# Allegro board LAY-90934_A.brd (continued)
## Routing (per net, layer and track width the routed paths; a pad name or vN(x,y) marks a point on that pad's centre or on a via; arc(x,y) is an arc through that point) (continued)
QSPIA_SCLK: length 30.4
  TOP w0.086: U29.1 113.5,31.53 v1(113.92,31.12) ; U20.6 122.55,51.31 TP61.1 v1(121.22,51.44)
  BOTTOM w0.086: v1(113.92,31.12) 119,31.12 121.92,34.04 121.92,44.2 121.41,44.7 121.41,51.24 v1(121.22,51.44)
RC_BT_MODE0: length 7
  TOP w0.086: R109.1 v1(67.82,64.26) SW3.7
  BOTTOM w0.086: R421.1 v1(67.82,64.26) 66.09,62.54 U63.15
RC_BT_MODE1: length 5.6
  TOP w0.086: SW3.5 v1(66.55,64.26) R108.1
  BOTTOM w0.086: R422.1 v1(66.55,64.26) 65.22,62.94 U63.14
RC_BT_MODE2: length 4.5
  TOP w0.086: R107.1 v1(65.28,64.26) SW3.3
  BOTTOM w0.086: R423.1 v1(65.28,64.26) 65.28,63.63 64.99,63.34 U63.13
RC_BT_MODE3: length 3.9
  TOP w0.086: SW3.1 v1(64.01,64.39) R106.1
  BOTTOM w0.086: R424.1 v1(64.01,64.39) 63.85,64.23 U63.12
RC_NSEL: length 98.5
  TOP w0.086: v1(53.53,63.18) 52.32,64.39 49.53,64.39 49.28,64.64 42.67,64.64 39.05,61.02 Q1.3 37.53,61.02 35.56,62.99 33.54,62.99 D5.C 33.03,63.11 32.64,63.5 R103.2 29.97,63.89 29.84,64.01 22.1,64.01 13.34,55.25 13.34,47.37 14.99,45.72 14.99,43.18 21.46,36.7 21.46,28.83 v1(20.96,28.32)
  BOTTOM w0.086: v1(53.53,63.18) 53.53,63.19 55.94,63.19 60.96,58.17 65.02,58.17 65.41,58.55 65.41,61.72 64.99,62.14 U63.16 63.87,62.14 U63.1 ; U65.12 v1(20.96,28.32)
RC_SEL: length 3.5
  TOP w0.086: U14.4 39.5,64.27 v1(38.99,63.75) 38.87,63.64 Q1.1
  BOTTOM w0.086: v1(38.99,63.75) 39.37,64.14 R426.1 R425.2
REG_FEQ: length 1.7
  TOP w0.254: R309.2 43.82,21.85 v1(44.96,21.85) U39.29
REG_FT_1V8: length 6.4
  TOP w0.203: U28.49 4.63,36.52 4.45,36.7 TP115.1
  TOP w0.254: U28.49 6.34,36.52 v1(6.41,36.45)
  BOTTOM w0.381: v1(6.41,36.45) 7.11,36.45 7.15,36.42 C268.1 7.15,34.38 L15.2
REG_MODE: length 4.1
  TOP w0.254: U39.2 v1(46.76,18.92)
  BOTTOM w0.254: R472.2 47.12,21.17 47.11,21.16 R473.2 47.11,19.28 v1(46.76,18.92)
REG_ST: length 1.2
  TOP w0.254: C125.2 46.26,25.5 U39.24
RTC_CLKO: length 14
  TOP w0.086: TP25.1 v1(20.24,66.35) 20.24,67.39 19.81,67.82 18.48,67.82 18.28,68.02 U12.6 ; R146.2 v1(18.67,58.04)
  BOTTOM w0.086: v1(18.67,58.04) 20.24,59.61 v1(20.24,66.35)
RTC_NINTA: length 139.2
  TOP w0.086: v1(49.09,60.77) 49.28,60.58 57.66,60.58 58.8,59.44 65.41,59.44 68.2,56.64 68.2,44.58 69.47,43.31 v1(69.47,42.04) ; R138.2 v1(114.17,56.26)
  TOP w0.254: U12.13 17.28,72.78 TP9.1 v1(17.78,73.86) R20.2
  BOTTOM w0.086: v1(17.78,73.86) 18.21,74.3 44.2,74.3 45.72,72.77 45.72,62.99 46.23,62.48 47.75,62.48 49.09,61.15 v1(49.09,60.77) ; v1(114.17,56.26) 115.19,55.25 115.19,49.66 114.68,49.15 109.09,49.15 101.85,41.91 84.2,41.91 83.44,41.15 70.36,41.15 v1(69.47,42.04)
RTC_SCL: length 2.7
  TOP w0.254: U12.2 16.28,67.96 v1(16.01,67.69) R81.2 R80.2
RTC_SDA: length 2.7
  TOP w0.254: R85.2 R84.2 v1(18.03,67.69) 17.78,67.94 U12.5
S1_LPD4_VDD2: length 15.5
  TOP w0.203: R134.1 v1(52.07,57.79)
  BOTTOM w0.203: v1(52.07,57.79) 51.56,57.28 51.56,56.39 53.47,54.48 59.94,54.48 61.21,53.21 61.21,51.69 v1(61.72,51.18)
S1_VDD_SOC_0V8: length 28.3
  BOTTOM w0.203: R466.1 42.35,30.29 59.88,30.29 62.99,33.4 62.99,38.1 v1(63.88,38.99)
SAI1_DAC_MCLK: length 36
  TOP w0.086: U31.12 126.4,31.53 126.11,31.24 v1(126.11,31.12) ; TP148.1 v1(101.98,24.38) R285.1
  BOTTOM w0.086: v1(101.98,24.38) 101.98,23.24 102.49,22.73 110.62,22.73 114.43,26.54 127.09,26.54 127.76,27.21 127.76,30.23 126.87,31.12 v1(126.11,31.12)
SAI1_DAC_TXC: length 39.7
  TOP w0.086: TP146.1 101.6,25.4 v1(101.98,25.4) R278.1 ; U31.3 v1(128.91,32.33)
  BOTTOM w0.086: v1(101.98,25.4) 101.47,24.89 101.47,23.37 102.36,22.48 116.46,22.48 119.13,25.15 126.87,25.15 129.03,27.31 129.03,30.73 128.52,31.24 128.52,31.95 v1(128.91,32.33)
SAI1_DAC_TXD: length 25.2
  TOP w0.086: v1(125.79,32.89) 125.96,32.73 U31.9 ; R297.1 v1(114.62,22.99) TP150.1
  BOTTOM w0.086: v1(114.62,22.99) 117.03,25.4 126.75,25.4 128.78,27.43 128.78,30.61 126.49,32.89 v1(125.79,32.89)
SAI1_DAC_TXFS: length 20.1
  TOP w0.086: TP149.1 115,24 v1(114.62,24) R287.1 ; v1(128.27,30.23) 127.98,30.52 U31.16
  BOTTOM w0.086: v1(114.62,24) 116.9,26.29 127.25,26.29 128.27,27.31 v1(128.27,30.23)
SAI1_EN_B: length 31.3
  TOP w0.086: R123.2 v1(122.81,59.94)
  BOTTOM w0.086: R465.1 123.95,31.76 123.95,48.26 121.67,50.55 121.67,58.8 v1(122.81,59.94)
SAI1_RXD0: length 70.7
  TOP w0.086: U31.10 125.93,32.33 v1(125.86,32.26) ; v1(104.01,66.23) 104.01,65.38 102.64,64.01 101.35,64.01 97.66,60.33 97.66,58.29 96.99,57.62 96.99,56.58 U1.B14
  BOTTOM w0.086: v1(125.86,32.26) 125.35,32.77 125.35,33.66 124.46,34.54 124.46,48.51 122.94,50.04 122.94,57.53 123.57,58.17 123.57,64.39 123.95,64.77 123.95,65.79 123.44,66.29 120.27,66.29 119.13,65.15 105.09,65.15 v1(104.01,66.23)
SAI1_SEL: length 64.5
  TOP w0.086: SW4.3 R66.1 129.29,67.82 129.29,68.2 129.03,68.45 127.89,68.45 127.38,67.95 120.4,67.95 119.95,68.39 v1(118.94,68.39) R73.2 ; v1(129.95,29.78) 128.08,29.78 127.58,30.28 U31.15
  BOTTOM w0.086: v1(118.94,68.39) 119.19,68.64 120.46,68.64 121.28,67.82 124.21,67.82 125.48,66.55 125.48,64.01 125.09,63.63 125.09,57.4 124.46,56.77 124.46,50.8 125.98,49.28 125.98,37.97 130.18,33.78 130.18,30.01 v1(129.95,29.78)
SAI1_TXC: length 70
  TOP w0.086: v1(105.47,66.93) 105.47,66.15 102.82,63.5 101.6,63.5 98.17,60.07 98.17,58.04 97.49,57.35 97.49,56.72 97.23,56.47 U1.B15 ; v1(128.27,34.04) 127.98,33.75 U31.5
  BOTTOM w0.086: v1(128.27,34.04) 125.22,37.08 125.22,48.9 123.7,50.42 123.7,57.15 124.33,57.79 124.33,64.01 124.71,64.39 124.71,66.17 123.83,67.06 112.52,67.06 112.01,66.55 105.85,66.55 v1(105.47,66.93)
SAI1_TXD0: length 131.9
  TOP w0.086: v1(70.87,72.45) 71.12,72.2 71.12,62.1 69.22,60.2 65.66,60.2 TP33.1 64.01,61.85 R106.2 ; v1(105.16,67.44) 105.03,67.31 105.03,66.05 102.73,63.75 101.47,63.75 97.92,60.2 97.92,58.17 97.23,57.48 U1.A15 ; U31.7 127.18,33.86 v1(126.87,34.16)
  BOTTOM w0.086: v1(70.87,72.45) 71.44,73.03 78.23,73.03 78.61,72.64 84.2,72.64 85.47,73.91 92.33,73.91 92.96,73.28 95,73.28 96.65,71.63 96.65,70.49 97.03,70.1 97.28,70.1 99.57,72.39 102.36,72.39 104.9,69.85 104.9,67.69 v1(105.16,67.44) 105.03,67.31 105.03,66.8 105.54,66.29 112.14,66.29 112.65,66.8 123.7,66.8 124.46,66.04 124.46,64.52 124.08,64.14 124.08,57.91 123.44,57.28 123.44,50.29 124.97,48.77 124.97,36.07 v1(126.87,34.16)
SAI1_TXFS: length 133.7
  TOP w0.086: U31.2 129.04,31.93 v1(129.22,31.75) ; v1(70.61,71.88) 70.61,61.98 69.09,60.45 66.8,60.45 TP34.1 66.04,62.11 R107.2 ; U1.A14 96.73,57.75 97.41,58.42 97.41,60.45 101.22,64.26 102.55,64.26 103.5,65.21 103.5,66.29 103.95,66.74 v1(104.52,66.74)
  BOTTOM w0.086: v1(129.22,31.75) 129.41,31.94 129.41,32.51 128.4,33.53 126.87,33.53 124.71,35.69 124.71,48.64 123.19,50.17 123.19,57.4 123.83,58.04 123.83,64.26 124.21,64.64 124.21,65.91 123.57,66.55 112.78,66.55 112.27,66.04 105.22,66.04 v1(104.52,66.74) 104.65,66.87 104.65,69.72 102.23,72.14 99.69,72.14 97.41,69.85 96.9,69.85 96.39,70.36 96.39,71.5 94.87,73.03 92.84,73.03 92.2,73.66 85.6,73.66 84.33,72.39 78.49,72.39 78.11,72.77 71.75,72.77 70.87,71.88 v1(70.61,71.88)
SAI3_EN_B: length 18.9
  TOP w0.086: R52.2 127.76,70.1 v1(127.13,69.47) 127.13,68.58 126.75,68.2 120.52,68.2 119.63,69.09 v1(119.13,69.09) ; R68.2 v1(113.16,68.39)
  BOTTOM w0.086: v1(113.16,68.39) 113.86,69.09 v1(119.13,69.09) ; v1(127.13,69.47) 127.13,69.85 127.29,70.01 U59.13
SAI3_TX/RX_SEL: length 12.9
  TOP w0.086: R99.2 126.75,65.02 v1(127.19,65.47) ; R50.1 v1(126.75,70.99)
  BOTTOM w0.086: U59.15 126.93,70.81 v1(126.75,70.99) 126.36,70.61 126.36,69.09 127.19,68.26 v1(127.19,65.47)
SAI3_TX_SYNC: length 98.8
  TOP w0.086: v1(105.92,69.34) 106.17,69.09 106.17,66.17 101.22,61.21 v1(100.97,61.21) ; v2(96.23,55.31) 96.21,55.33 U1.D12 ; R108.2 67.95,61.47 TP32.1 70.1,62.48 v1(70.1,68.96)
  BOTTOM w0.086: v1(105.92,69.34) 107.31,69.34 109.98,72.01 109.98,73.15 110.74,73.91 111.63,73.91 112.01,73.53 112.52,73.53 113.41,74.42 118.11,74.42 119.76,72.77 122.94,72.77 123.76,71.95 127.63,71.95 128.33,72.64 128.78,72.64 128.98,72.44 U59.3 ; v1(70.1,68.96) 70.23,69.09 84.07,69.09 85.85,67.31 91.69,67.31 92.2,66.8 92.2,62.23 93.22,61.21 v1(100.97,61.21) 102.11,60.07 102.11,58.29 101.73,57.91 101.73,56.64 100.58,55.5 96.42,55.5 v2(96.23,55.31)
SAI3_TXBCLK/RXBCLK: length 16.6
  TOP w0.086: v1(128.58,72.24) 129.37,73.03 134.62,73.03 135.89,74.3 135.89,78.87 137.16,80.14 J4.36
  BOTTOM w0.086: U59.2 v1(128.58,72.24)
SAI3_TXSYNC/RXSYNC: length 13.1
  TOP w0.086: v1(130.81,71.37) 131.95,72.52 135.89,72.52 137.41,74.04 139.45,74.04 139.7,74.3 J4.37
  BOTTOM w0.086: U59.5 130.65,71.21 v1(130.81,71.37)
SD1_CLK: length 27.4
  TOP w0.086: U1.U11 95.23,43.96 96.01,43.18 96.01,42.42 100.58,37.85 TP110.1 105.66,36.96 111.12,36.96 111.51,37.34 111.51,39.15 111.38,39.28 111.01,39.28 U25.M6
SD1_CMD: length 27.3
  TOP w0.086: U25.M5 110.26,39.6 109.59,40.27 105.93,40.27 TP107.1 104.77,39.11 R239.2 102.99,39.11 102.87,38.99 102.87,38.35 102.74,38.23 102.62,38.23 102.49,38.35 102.49,38.9 102.4,38.99 102.2,38.99 102.11,38.9 102.11,38.35 101.98,38.23 101.85,38.23 101.73,38.35 101.73,39.02 101.64,39.12 101.44,39.12 101.35,39.02 101.35,38.74 101.22,38.61 101.09,38.61 100.97,38.74 100.71,38.74 100.58,38.61 100.33,38.61 96.39,42.55 96.39,43.31 95.57,44.13 95.57,47.05 95.48,47.14 95.48,49.08 U1.T11
SD1_DATA0: length 26.9
  TOP w0.086: U1.T13 96.48,49.08 96.48,47.66 96.84,47.31 96.84,44.89 99.57,42.16 101.35,42.16 101.47,42.29 101.47,42.8 101.58,42.91 R223.2 103.52,42.93 TP90.1 105.95,42.93 106.05,43.02 106.05,43.22 105.95,43.31 105.12,43.31 105.03,43.4 105.03,43.6 105.12,43.69 106.59,43.69 106.68,43.78 106.68,43.98 106.59,44.07 106.01,44.07 105.92,44.16 105.92,44.36 106.01,44.45 107.73,44.45 107.82,44.54 107.82,44.74 107.73,44.83 106.64,44.83 106.55,44.92 106.55,45.12 106.64,45.21 108.57,45.21 U25.A3
SD1_DATA1: length 27
  TOP w0.086: U25.A4 109.76,45.06 108.84,45.97 103.34,45.97 103.25,45.88 103.25,45.68 103.34,45.59 105.7,45.59 105.79,45.5 105.79,45.3 105.7,45.21 102.45,45.21 102.36,45.12 102.36,44.92 102.45,44.83 102.78,44.83 102.87,44.74 102.87,44.54 102.78,44.45 101.69,44.45 101.6,44.36 101.6,44.16 101.69,44.07 102.02,44.07 102.11,43.98 102.11,43.78 102.02,43.69 99.06,43.69 97.47,45.28 97.47,47.43 96.99,47.92 96.99,49.08 U1.T14
SD1_DATA2: length 26.9
  TOP w0.086: U1.T15 97.23,49.2 97.48,48.95 97.48,48.19 98.04,47.63 98.68,47.63 98.81,47.5 98.81,44.96 99.44,44.32 100.58,44.32 101.92,45.66 101.92,46.55 102.11,46.74 112.18,46.74 112.27,46.64 112.27,46.45 112.18,46.36 110.58,46.36 110.49,46.26 110.49,46.07 110.58,45.97 111.67,45.97 111.76,45.88 111.76,45.68 111.67,45.59 110.49,45.59 110.26,45.36 U25.A5
SD1_DATA3: length 26.8
  TOP w0.086: U25.B2 108.51,44.27 108.03,44.27 107.82,44.07 107.44,44.07 106.43,43.05 106.43,42.16 106.3,42.04 106.17,42.04 106.05,42.16 106.05,42.45 105.95,42.55 105.76,42.55 105.66,42.45 105.66,42.26 105.57,42.16 105.41,42.16 105.16,42.42 102.74,42.42 102.62,42.29 102.62,41.75 102.52,41.66 102.33,41.66 102.23,41.75 102.23,42.45 102.14,42.55 101.95,42.55 101.85,42.45 101.85,40.86 101.76,40.77 101.56,40.77 101.47,40.86 101.47,41.69 101.38,41.78 101.18,41.78 101.09,41.69 101.09,40.86 101,40.77 100.8,40.77 100.71,40.86 100.71,41.69 100.62,41.78 100.42,41.78 100.33,41.69 100.33,41.24 100.24,41.15 100.08,41.15 99.95,41.28 99.95,41.66 99.82,41.78 99.44,41.78 96.52,44.7 96.52,47.24 96.23,47.53 U1.U13
SD1_DATA4: length 27.1
  TOP w0.086: U25.B3 109.01,43.78 107.66,43.78 107.44,43.56 107.44,42.93 107.57,42.8 107.86,42.8 107.95,42.71 107.95,42.51 107.86,42.42 106.9,42.42 106.81,42.33 106.81,42.13 106.9,42.04 107.86,42.04 107.95,41.95 107.95,41.75 107.86,41.66 105.41,41.66 104.97,42.1 103.19,42.1 103,41.91 103,40.99 102.91,40.89 102.71,40.89 102.62,40.99 102.62,41.18 102.52,41.28 102.33,41.28 102.23,41.18 102.23,40.48 102.14,40.39 100.33,40.39 96.2,44.51 96.2,47.18 95.98,47.4 95.98,49.08 U1.T12
SD1_DATA5: length 26.8
  TOP w0.086: U1.U14 96.73,47.79 97.16,47.37 97.16,45.09 99.69,42.55 101,42.55 101.09,42.64 101.09,42.83 101,42.93 99.79,42.93 99.69,43.02 99.69,43.22 99.79,43.31 102.91,43.31 103,43.4 103,43.6 102.91,43.69 102.58,43.69 102.49,43.78 102.49,43.98 102.58,44.07 104.24,44.07 104.33,44.16 104.33,44.36 104.24,44.45 103.34,44.45 103.25,44.54 103.25,44.74 103.34,44.83 106.08,44.83 106.17,44.92 106.17,45.47 106.3,45.59 108.71,45.59 109.5,44.8 109.5,44.29 109.76,44.04 U25.B4
SD1_DATA6: length 26.8
  TOP w0.086: U1.U15 97.23,48.05 97.79,47.5 97.79,45.43 97.88,45.34 98.08,45.34 98.17,45.43 98.17,47.15 98.26,47.24 98.46,47.24 98.55,47.15 98.55,44.7 99.25,44.01 101.03,44.01 101.22,44.2 101.22,44.45 101.6,44.83 101.85,44.83 101.98,44.96 101.98,45.21 102.23,45.47 102.23,46.26 102.33,46.36 102.52,46.36 102.62,46.26 102.62,45.68 102.71,45.59 102.91,45.59 103,45.68 103,46.23 103.12,46.36 110.02,46.36 110.11,46.26 110.11,46.07 110.02,45.97 109.63,45.97 109.54,45.88 109.54,45.68 109.63,45.59 109.91,45.59 110,45.5 110,44.28 U25.B5
SD1_DATA7: length 27
  TOP w0.086: U1.U16 97.73,48.32 98.17,47.88 98.81,47.88 99.06,47.63 99.06,45.21 99.63,44.64 100.39,44.64 101.66,45.91 101.66,46.8 101.98,47.12 112.27,47.12 112.65,46.74 112.65,45.68 112.56,45.59 112.23,45.59 112.14,45.5 112.14,45.3 112.23,45.21 113.45,45.21 113.54,45.12 113.54,44.92 113.45,44.83 111.13,44.83 111,44.7 111,44.27 U25.B6
SD1_STROBE: length 21.8
  TOP w0.086: U1.U12 95.73,47.27 95.88,47.12 95.88,44.32 97.03,43.18 TP93.1 100.08,39.75 103.5,39.75 105.03,41.28 109.41,41.28 109.66,41.03 U25.H5
SD2_CLK: length 31.4
  TOP w0.086: U1.M16 97.99,51.08 103.28,51.08 103.95,51.75 116.14,51.75 117.98,53.59 124.46,53.59 125.23,52.83 TP50.1 125.77,52.83 125.86,52.92 125.86,53.25 125.95,53.34 126.15,53.34 126.24,53.25 126.24,52.96 126.36,52.83 R171.1
SD2_CMD: length 32
  TOP w0.086: R153.1 R151.2 126.49,56.13 126.24,55.88 126.24,55.25 126.11,55.12 TP44.1 125.35,55.12 124.21,53.98 117.73,53.98 115.82,52.07 103.89,52.07 103.15,51.33 U1.M17
SD2_DATA0: length 31.9
  TOP w0.086: U1.N17 103.41,50.83 104.01,51.44 116.46,51.44 118.24,53.21 124.21,53.21 TP55.1 125.73,52.07 125.86,52.2 126.5,52.2 R173.2 R177.1
SD2_DATA1: length 31.7
  TOP w0.086: R186.1 125.22,51.31 125.22,51.69 124.08,52.83 118.49,52.83 116.78,51.12 104.08,51.12 103.54,50.58 97.99,50.58 U1.N16
SD2_DATA2: length 31.6
  TOP w0.086: U1.L17 102.89,51.83 103.76,52.71 115.19,52.71 117.22,54.74 124.21,54.74 126.36,56.9 126.36,57.53 R133.1
SD2_DATA3: length 31.5
  TOP w0.086: U1.L16 97.99,51.58 103.02,51.58 103.82,52.39 115.51,52.39 117.47,54.36 124.21,54.36 R147.1
SD2_NCD: length 51.4
  TOP w0.086: R218.2 139.25,43.5 U22.4 136.59,43.5 v1(136.14,43.94) 132.72,43.94 132.59,44.07 R217.1 132.09,43.94 128.78,43.94 124.97,47.75 124.97,51.44 123.95,52.45 118.74,52.45 117.86,51.56 117.86,50.93 117.54,50.61 104.33,50.61 v1(104.27,50.67) ; v2(96.21,50.34) 96.2,50.33 U1.P12
  BOTTOM w0.086: v2(96.21,50.34) 97.46,50.34 97.79,50.67 v1(104.27,50.67)
SD2_NDET: length 12.3
  TOP w0.086: J6.9 129.05,48.44 D14.1 129.03,48.35 R196.2 129.03,45.72 129.03,45.72 TP82.1 v1(130.05,44.96) ; R217.2 v1(133.99,44.45) U22.2
  BOTTOM w0.086: v1(133.99,44.45) 133.48,44.96 v1(130.05,44.96)
SD2_NRST: length 60.5
  TOP w0.086: v1(73.02,39.62) 76.9,43.5 v1(82.49,43.5) ; U1.P10 94.32,50.33 v2(94.28,50.29) ; R236.1 v1(44.2,37.72)
  BOTTOM w0.086: v2(94.28,50.29) 94.28,50.29 94.3,50.27 94.3,50.27 95,49.57 R312.2 91.83,45.97 90.3,45.97 88.01,43.69 82.68,43.69 v1(82.49,43.5) ; v1(73.02,39.62) 72.64,40.01 61.34,40.01 58.99,37.66 54.23,37.66 52.64,36.07 47.75,36.07 46.1,37.72 v1(44.2,37.72)
SD2_VSEL: length 107.6
  TOP w0.086: v1(104.14,35.94) 114.17,35.94 115.19,36.96 115.19,44.7 112.01,47.88 100.08,47.88 99.82,48.13 98.3,48.13 97.99,48.45 97.99,48.95 97.85,49.08 97.63,49.08 97.49,49.23 97.49,49.24 97.48,49.24 97.48,49.95 97.35,50.08 96.98,50.08 U1.P14 ; v1(47.82,38.38) 47.82,40.14 48.29,40.61 48.29,41.12 48.19,41.22 U23.35
  BOTTOM w0.086: v1(104.14,35.94) 98.68,41.4 88.01,41.4 86.36,39.75 82.68,39.75 81.15,38.23 79.76,38.23 77.09,40.89 60.71,40.89 58.36,38.54 53.84,38.54 52.37,37.08 48.64,37.08 47.82,37.91 v1(47.82,38.38)
SD3_CLK: length 34.4
  TOP w0.086: U1.T16 97.87,49.33 98.12,49.08 99.38,49.08 100.27,48.2 112.2,48.2 115.57,44.83 115.57,36.7 v1(113.54,34.67) ; U29.2 v1(114.05,31.93)
  BOTTOM w0.086: v1(113.54,34.67) 113.54,32.44 v1(114.05,31.93)
SD3_CMD: length 36.7
  TOP w0.086: U29.5 113.12,33.62 113.28,33.78 113.66,33.78 114.43,33.02 115.73,33.02 115.82,33.11 115.82,33.31 115.73,33.4 114.55,33.4 114.43,33.53 114.43,34.93 115.95,36.45 115.95,44.96 112.39,48.51 100.46,48.51 99.64,49.33 U1.T17
SD3_DATA0: length 39.5
  TOP w0.086: U1.R16 97.98,49.58 99.9,49.58 100.65,48.83 112.59,48.83 116.33,45.09 116.33,35.81 116.2,35.69 115.66,35.69 115.57,35.6 115.57,35.4 115.66,35.31 116.24,35.31 116.33,35.21 116.33,35.02 116.24,34.93 114.9,34.93 114.81,34.83 114.81,33.87 114.9,33.78 115.1,33.78 115.19,33.87 115.19,34.45 115.28,34.54 115.48,34.54 115.57,34.45 115.57,33.87 115.66,33.78 115.86,33.78 115.95,33.87 115.95,34.42 116.08,34.54 116.59,34.54 116.77,34.36 U30.7
SD3_DATA1: length 40.5
  TOP w0.086: U30.10 v1(115.44,32.33) ; v1(116.78,35.43) 116.71,35.5 116.71,45.21 112.78,49.15 100.84,49.15 100.15,49.83 U1.R17
  BOTTOM w0.086: v1(116.78,35.43) 115.95,34.61 115.95,33.78 116.2,33.53 117.13,33.53 117.22,33.44 117.22,33.24 117.13,33.15 115.53,33.15 115.44,33.06 115.44,32.86 115.53,32.77 117.13,32.77 117.22,32.68 117.22,32.47 117.13,32.39 115.5,32.39 v1(115.44,32.33)
SD3_DATA2: length 42.3
  TOP w0.086: U30.2 v1(118.49,31.93) ; v1(117.16,34.67) 117.22,34.73 117.22,35.69 117.09,35.81 117.09,45.34 112.97,49.47 101.03,49.47 100.41,50.08 97.99,50.08 U1.P16
  BOTTOM w0.086: v1(118.49,31.93) 118.36,32.06 118.36,34.83 118.27,34.93 118.07,34.93 117.98,34.83 117.98,32.1 117.89,32 117.69,32 117.6,32.1 117.6,34.23 v1(117.16,34.67)
SD3_DATA3: length 43.6
  TOP w0.086: U1.P17 100.67,50.33 101.22,49.78 113.16,49.78 117.47,45.47 117.47,35.02 117.57,34.93 117.76,34.93 117.86,35.02 117.86,37.12 117.95,37.21 118.15,37.21 118.24,37.12 118.24,34.89 118.33,34.8 118.53,34.8 118.62,34.89 118.62,36.36 118.71,36.45 118.91,36.45 119,36.36 119,34.54 118.87,34.42 117.73,34.42 117.57,34.26 U30.5
SD3_NRST: length 84.6
  TOP w0.086: R111.1 v1(122.81,62.99) R110.2 ; v1(117.47,46.61) 118.11,45.97 118.11,38.23 119.89,36.45 119.89,27.81 120.4,27.31 120.4,21.78 120.27,21.65 118.74,21.65 118.62,21.53 118.62,16.95 115.44,13.78 115.44,8.51 120.02,3.94 131.7,3.94 TP178.1 132.58,4.45 133.54,5.4 J8.23
  BOTTOM w0.086: v1(117.47,46.61) 116.71,47.37 116.71,54.23 121.03,58.55 121.03,61.21 v1(122.81,62.99)
SD3_NWAKE: length 38.9
  TOP w0.086: R142.2 v1(118.24,56.45) ; v1(116.2,48.51) 118.43,46.29 118.43,38.42 120.21,36.64 120.21,27.88 120.78,27.31 120.78,23.37 120.9,23.25 R290.2 121.42,23.11 121.67,23.11 122.03,22.75 U41.10
  BOTTOM w0.086: v1(118.24,56.45) 116.46,54.67 116.46,48.77 v1(116.2,48.51)
SD3_QSPI_SEL: length 113
  TOP w0.086: v1(112.97,30.04) 112.72,30.28 U29.15 ; SW4.1 v1(129.92,69.09) R62.1 ; U30.15 117.17,30.28 v1(117.47,29.97) ; v1(78.36,38.1) 77.6,37.34 R248.1 ; v1(127.63,65.91) 123.63,65.91 v1(123.19,65.47) 123.19,66.04 R75.2
  BOTTOM w0.086: v1(112.97,30.04) 106.36,36.64 106.36,44.89 109.6,48.13 115.19,48.13 116.2,49.15 116.2,54.86 117.73,56.39 117.73,59.82 123.19,65.28 v1(123.19,65.47) ; v1(112.97,30.04) 113.54,30.61 116.84,30.61 v1(117.47,29.97) ; v1(112.97,30.04) 112.52,29.59 109.6,29.59 98.04,41.15 88.14,41.15 86.49,39.5 82.8,39.5 81.28,37.97 78.49,37.97 v1(78.36,38.1) ; v1(129.92,69.09) 129.92,67.18 128.65,65.91 v1(127.63,65.91)
SD_CLK: length 3.9
  TOP w0.086: J6.5 129.86,52.84 D11.1 128.85,52.45 128.01,52.45 R171.2
SD_CMD: length 3.3
  TOP w0.086: J6.3 130.92,55.05 D9.1 127.7,55.05 R153.2
SD_DATA0: length 3.4
  TOP w0.086: J6.7 130.89,50.6 D12.1 127.83,50.6 R177.2
SD_DATA1: length 3.4
  TOP w0.086: R186.2 127.83,49.46 D13.1 130.84,49.46 J6.8
SD_DATA2: length 3.6
  TOP w0.086: R133.2 128.34,57.33 D6.1 130.84,57.33 J6.1
SD_DATA3: length 3.7
  TOP w0.086: J6.2 130.04,56.14 129.59,56.59 D7.1 128.06,56.59 R147.2
SPI3_CLK: length 67.4
  TOP w0.086: U43.9 129.79,22.1 127.77,24.13 125.85,24.13 121.79,28.19 121.79,36.96 125.22,40.39 125.22,43.12 v1(126.68,44.58) ; v1(118.43,69.66) 118.11,69.34 115.82,69.34 115.48,69.69 U9.1
  BOTTOM w0.086: v1(118.43,69.66) 119.82,69.66 121.41,68.07 124.33,68.07 125.73,66.68 125.73,64.26 126.24,63.75 126.24,61.6 125.6,60.96 125.6,55.63 124.97,54.99 124.97,51.05 127.06,48.96 127.06,48.2 126.49,47.63 126.49,44.77 v1(126.68,44.58)
SPI3_CS0: length 66.3
  TOP w0.086: v1(117.03,70.04) 116.68,70.4 U9.4 ; U43.10 129.39,22 127.64,23.75 125.85,23.75 121.48,28.13 121.48,37.15 124.97,40.64 124.97,43.82 126.36,45.21 v1(126.94,45.21)
  BOTTOM w0.086: v1(117.03,70.04) 117.22,69.85 117.98,69.85 118.24,70.1 119.76,70.1 121.54,68.33 124.46,68.33 125.98,66.8 125.98,64.39 126.49,63.88 126.49,61.47 125.86,60.83 125.86,55.5 125.22,54.86 125.22,51.18 127.32,49.09 127.32,45.59 v1(126.94,45.21)
SPI3_MISO: length 66.5
  TOP w0.086: U9.8 117.57,71.97 117.79,72.2 118.17,72.2 118.62,71.76 v1(118.62,71.5) ; U43.8 130.19,22.21 127.9,24.51 125.86,24.51 122.11,28.26 122.11,36.77 125.48,40.13 125.48,42.8 v1(127.32,44.64)
  BOTTOM w0.086: v1(127.32,44.64) 127.57,44.89 127.57,49.21 126.11,50.67 126.11,60.71 126.75,61.34 126.75,64.01 126.24,64.52 126.24,68.07 124.84,69.47 120.9,69.47 118.87,71.5 v1(118.62,71.5)
SPI3_MOSI: length 69.6
  TOP w0.086: U43.7 130.59,22.32 128.02,24.89 125.86,24.89 122.43,28.32 122.43,36.58 125.73,39.88 125.73,42.42 v1(127.25,43.94) ; U9.11 115.88,72.57 116.08,72.77 116.08,73.03 116.4,73.34 116.97,73.34 v1(117.35,72.96)
  BOTTOM w0.086: v1(127.25,43.94) 127.83,44.51 127.83,49.34 126.36,50.8 126.36,60.58 127,61.21 127,64.14 126.49,64.64 126.49,68.2 124.21,70.49 123.7,70.49 123.44,70.23 120.78,70.23 118.05,72.96 v1(117.35,72.96)
STAR_I2C_SCL: length 8.2
  TOP w0.086: J3.3 J3.4 64.77,74.8 v1(64.26,74.3) R28.2
STAR_I2C_SDA: length 8.1
  TOP w0.086: J3.5 J3.6 67.31,74.55 v1(67.56,74.3) R31.2
SUSCLK: length 2.2
  TOP w0.086: J8.50 v1(126.79,15.24) 126.79,16.09 R349.1
SUSCLK_32K: length 2.7
  TOP w0.086: R350.2 127.63,16.89 R349.2 v1(126.75,17.53) Q9.3
SYS_NRST: length 114.4
  TOP w0.086: D22.A v1(67.31,25.91) ; v1(44.96,52.32) 40.64,56.64 40.64,60.71 43.31,63.37 47.03,63.37 v1(47.22,63.18) 48.64,61.76 48.64,60.58 48.89,60.33 57.53,60.33 58.67,59.18 65.28,59.18 67.94,56.52 67.94,44.45 69.02,43.37 69.02,40.7 69.6,40.13 69.6,29.59 v1(69.34,29.34) ; R189.1 v3(45.21,50.17) ; R14.2 23.37,75.95 C17.1 v1(24.26,75.18)
  BOTTOM w0.086: v1(67.31,25.91) 69.34,27.94 v1(69.34,29.34) ; 47.22,66.05 46.6,66.05 46.23,66.42 46.23,73.28 44.7,74.8 24.64,74.8 v1(24.26,75.18) ; 47.22,66.05 R418.2 ; 47.22,66.05 v1(47.22,63.18) ; v1(44.96,52.32) 45.21,52.07 v3(45.21,50.17)
TAMPER0: length 58.4
  TOP w0.086: v2(93.23,55.37) 93.2,55.33 U1.D6 ; J1.3 56.26,81.69 R8.1 R9.2 57.79,78.73 60.45,76.07 60.45,67.06 v1(61.47,66.04)
  BOTTOM w0.086: v2(93.23,55.37) 93.6,55.73 93.6,56.64 85.34,64.9 82.93,64.9 82.3,65.53 69.98,65.53 69.09,66.42 61.85,66.42 v1(61.47,66.04)
TAMPER1: length 60.9
  TOP w0.086: J1.4 55.28,78.77 R7.1 R6.2 53.84,78.73 53.59,78.49 53.59,77.22 54.36,76.45 58.42,76.45 60.07,74.8 60.07,66.8 v1(60.83,66.04) ; v2(94.19,55.37) 94.16,55.33 U1.D8
  BOTTOM w0.086: v2(94.19,55.37) 93.85,55.7 93.85,56.77 85.47,65.15 83.06,65.15 82.42,65.79 70.1,65.79 69.22,66.68 61.47,66.68 v1(60.83,66.04)
TCPC1_NINT: length 116.6
  TOP w0.086: v1(70.55,42.04) 70.36,41.85 70.36,29.08 69.72,28.45 65.91,28.45 64.64,27.18 33.4,27.18 31.12,24.89 31.12,20.45 31.37,20.19 33.27,20.19 33.66,19.81 33.66,18.42 33.53,18.29 R331.2 31.9,17.17 U48.10 ; R136.1 v1(112.14,56.64)
  BOTTOM w0.086: v1(70.55,42.04) 83.57,42.04 83.95,42.42 89.66,42.42 91.12,43.88 97.6,43.88 98.3,43.18 102.36,43.18 112.14,52.96 v1(112.14,56.64)
TCPC_NINT: length 90.5
  TOP w0.086: v1(113.41,56.39) 113.16,56.64 R137.2 ; R373.2 64.77,11.18 v1(65.15,11.56) 65.79,12.19 TP169.1 67.82,11.68 70.48,11.68 70.85,12.05 U49.10 ; v1(73.91,23.62) 73.91,34.86 v1(80.64,41.59)
  BOTTOM w0.086: v1(80.64,41.59) 83.5,41.59 84.07,42.16 89.79,42.16 91.25,43.62 97.47,43.62 98.17,42.93 102.49,42.93 108.97,49.4 114.55,49.4 114.94,49.78 114.94,54.86 v1(113.41,56.39) ; v1(65.15,11.56) 65.15,13.21 69.34,17.4 69.34,19.05 v1(73.91,23.62)
TEMP_NINT: length 2.6
  TOP w0.086: R42.2 TP14.1 101.83,71.77 U11.C1
UART1_RXD: length 54.6
  TOP w0.086: v1(96.9,58.93) 96.9,58.29 96.49,57.88 96.49,56.58 U1.B13 ; v1(58.55,74.17) 58.6,74.12 TP186.1
  BOTTOM w0.086: v1(96.9,58.93) 95.12,58.93 91.95,62.1 91.95,66.68 91.57,67.06 85.72,67.06 83.95,68.83 70.87,68.83 70.48,68.45 69.79,68.45 69.09,69.15 61.53,69.15 60.32,70.36 60.32,73.41 59.56,74.17 v1(58.55,74.17) 58.2,74.17 57.43,73.4 R401.2
UART1_TXD: length 58.2
  TOP w0.086: v1(69.22,68.45) 69.6,68.07 69.6,63.37 TP29.1 67.82,62.87 R109.2 ; v1(96.39,58.42) 96.23,58.26 U1.A13 ; TP187.1 59.36,72.97 v1(59.08,73.25)
  BOTTOM w0.086: v1(96.39,58.42) 95.25,58.42 91.69,61.98 91.69,66.55 91.44,66.8 85.6,66.8 83.82,68.58 70.99,68.58 70.61,68.2 69.47,68.2 v1(69.22,68.45) 68.77,68.9 61.4,68.9 60.07,70.23 60.07,72.26 v1(59.08,73.25) 58.93,73.4 R400.2
UART5/JTAG_SEL: length 74.1
  TOP w0.086: v1(115.25,55.75) 115.51,55.5 122.81,55.5 129.28,61.97 R96.1 SW4.7 ; v1(80.01,38.67) 78.35,37.01 R248.2 78.43,35.23 U27.15
  BOTTOM w0.086: v1(115.25,55.75) 115.44,55.56 115.44,49.53 114.81,48.9 109.22,48.9 101.98,41.66 87.88,41.66 86.23,40.01 82.55,40.01 81.22,38.67 v1(80.01,38.67)
UART5_CTSI: length 71.9
  TOP w0.086: U27.16 79.28,34.83 v1(79.25,34.8) ; J8.34 130.79,14.84 132.21,16.26 132.21,21.72 128.27,25.66 125.85,25.66 124.46,27.05 v1(124.46,27.31)
  BOTTOM w0.086: v1(79.25,34.8) 80.77,34.8 83.95,37.97 88.52,37.97 90.17,39.62 97.16,39.62 109.73,27.05 124.21,27.05 v1(124.46,27.31)
UART5_RTSO: length 67.6
  TOP w0.086: v1(123.83,27.56) 123.83,27.31 125.86,25.27 128.15,25.27 131.83,21.6 131.83,16.38 130.29,14.85 J8.36 ; v1(82.2,36.8) 81.88,36.48 U27.9
  BOTTOM w0.086: v1(123.83,27.56) 123.06,28.32 108.84,28.32 97.28,39.88 90.04,39.88 88.39,38.23 83.63,38.23 v1(82.2,36.8)
UART5_RXD: length 70.5
  TOP w0.086: J8.22 133.79,14.54 132.97,15.37 132.97,21.98 128.53,26.42 126.11,26.42 v1(125.48,27.05) ; v1(81.53,33.93) 81.48,33.99 U27.3
  BOTTOM w0.086: v1(125.48,27.05) 125.22,26.8 109.6,26.8 97.03,39.37 90.3,39.37 88.65,37.72 85.09,37.72 83.31,35.94 83.06,35.94 81.53,34.42 v1(81.53,33.93)
UART5_TXD: length 71
  TOP w0.086: v1(80.26,36.83) 80.68,36.41 U27.12 ; v1(124.21,28.58) 124.97,27.81 124.97,26.92 125.85,26.04 128.4,26.04 132.59,21.85 132.59,16.13 131.29,14.84 J8.32
  BOTTOM w0.086: v1(80.26,36.83) 81.66,36.83 83.31,38.48 88.27,38.48 89.92,40.13 97.41,40.13 108.97,28.58 v1(124.21,28.58)
USB1_CC1: length 8.1
  TOP w0.086: v1(26.29,12.45) 26.8,11.94 U51.A2 ; v1(28.19,15.24) 29.85,16.89 30.61,16.89 30.7,16.8 U48.13
  BOTTOM w0.086: v1(26.29,12.45) 26.29,13.34 v1(28.19,15.24)
USB1_CC2: length 7.5
  TOP w0.086: U48.14 29.1,15.64 28.83,15.37 v1(28.83,14.22) 28.83,11.43 28.57,11.18 28.19,11.18 27.89,11.48 U51.C1 U51.C2 U51.B2
USB1_DN: length 117.5
  TOP w0.087: v1(73.29,60.71) 73.02,60.44 73.02,60.02 69.43,56.43 69.43,46.32 71.21,44.54 71.21,28.74 70.19,27.72 66.33,27.72 65.02,26.42 37.85,26.42 37.3,25.87 37.3,12.99 34.51,10.2 30.19,10.2 29.95,9.96 29.95,9.76 U55.C1 ; U1.A4 91.7,56.87 91.7,59.81 88.3,63.21 75.97,63.21 75.46,62.7 74.97,62.7 v1(74.85,62.82)
  BOTTOM w0.087: v1(73.29,60.71) 73.02,60.44 73.02,60.2 73.15,60.07 73.91,60.07 74.42,60.58 74.42,61.66 74.93,62.17 74.93,62.74 v1(74.85,62.82)
USB1_DP: length 117.5
  TOP w0.087: v1(72.55,60.71) 72.81,60.45 72.81,60.11 69.22,56.52 69.22,46.23 70.99,44.45 70.99,28.83 70.1,27.94 66.24,27.94 64.93,26.63 37.76,26.63 37.08,25.96 37.08,13.08 34.42,10.41 30.1,10.41 29.74,10.05 29.74,9.76 U55.C2 ; v1(75.37,62.3) 76.06,62.99 88.21,62.99 91.48,59.72 91.48,56.58 U1.B4
  BOTTOM w0.087: v1(72.55,60.71) 72.81,60.45 72.81,60.11 73.06,59.86 74,59.86 74.64,60.49 74.64,61.57 v1(75.37,62.3)
USB1_ID: length 15
  TOP w0.086: v1(84.71,64.39) TP26.1 R91.2 ; U1.D4 v2(92.23,55.33)
  BOTTOM w0.086: v1(84.71,64.39) 85.47,64.39 91.88,57.98 91.88,55.68 v2(92.23,55.33)
USB1_VBUS_3V3: length 92.7
  TOP w0.254: R280.2 28.06,25.65 28.45,26.04 31.62,26.04 33.15,27.56 64.52,27.56 65.79,28.83 69.6,28.83 69.98,29.21 69.98,43.43 68.58,44.83 68.58,58.29 72.01,61.72 83.43,61.72 R113.2
  TOP w0.381: R280.2 v1(28.7,25.02) 29.63,25.02 U36.1
USB1_VBUS_IN: length 2.4
  TOP w0.254: U47.G6 U47.F6 U47.E6 U47.D6 U47.C6
  TOP w0.381: 17.4,12.45 16.64,12.45
USB_CC1_PD: length 35.4
  TOP w0.086: v1(74.55,5.84) 74.56,5.85 R381.1
  TOP w0.087: J13.A5 v1(44.97,7.49) ; TP175.1 v1(48.89,8.64)
  BOTTOM w0.086: v1(44.97,7.49) 46.12,8.64 v1(48.89,8.64) 49.66,9.4 61.85,9.4 64.14,7.11 66.93,7.11 67.56,7.75 73.79,7.75 74.55,6.99 v1(74.55,5.84)
USB_CC1_PD_OVP: length 6.1
  TOP w0.254: U52.A1 76.83,8.94 76.83,5.97 v1(75.81,4.95) R383.2
USB_CC2_PD: length 27.3
  TOP w0.086: v1(68.83,5.85) R380.1
  TOP w0.087: J13.B5 v1(45.97,7.49) ; TP176.1 v1(49.53,8)
  BOTTOM w0.086: v1(68.83,5.85) 67.82,6.86 64.01,6.86 61.72,9.14 50.67,9.14 v1(49.53,8) 46.5,8 45.98,7.49 v1(45.97,7.49)
USB_CC2_PD_OVP: length 16.1
  TOP w0.254: R385.2 68.84,2.79 75.06,2.79 v1(77.34,5.08) 77.34,9.14 76.4,10.09 U52.B1
USB_DBG_CC1: length 2
  TOP w0.086: R377.1 13.73,8.12 J11.A5
USB_DBG_CC2: length 8.7
  TOP w0.086: R378.1 19.81,5.21 19.05,4.45 16.1,4.45 J11.B5
USB_DBG_DN: length 6.3
  TOP w0.087: J11.A7 14.73,7.74 v1(14.8,7.81) 14.59,8.02 14.59,8.78 U54.A1
  BOTTOM w0.087: J11.B7 14.08,6.56 14.14,6.63 14.33,6.63 14.47,6.49 14.59,6.49 14.66,6.55 14.66,6.84 15.28,7.46 15.28,8.13 15.12,8.29 14.71,8.29 14.59,8.17 14.59,8.02 v1(14.8,7.81)
USB_DBG_DP: length 6.3
  TOP w0.087: U54.A2 14.37,8.78 14.37,8.02 v1(14.16,7.81) 14.23,7.75 J11.A6
  BOTTOM w0.087: v1(14.16,7.81) 14.37,8.02 14.37,8.26 14.62,8.51 15.2,8.51 15.49,8.22 15.49,7.37 14.88,6.75 J11.B6
USB_I2C_SCL: length 132.7
  TOP w0.086: R359.2 36.13,14.92 36.13,13.4 v1(35.69,12.95) R368.2 ; R366.1 v1(68.96,13.34) 69.07,13.44 U49.8 ; R80.1 v1(14.48,65.85)
  BOTTOM w0.086: v1(14.48,65.85) 14.48,61.15 6.48,53.15 6.48,39.88 3.49,36.89 3.49,22.42 4.7,21.21 6.48,21.21 10.03,17.65 18.54,17.65 25.65,10.54 33.91,10.54 35.69,12.32 v1(35.69,12.95) 36.45,13.72 37.85,13.72 40.51,11.05 47.5,11.05 48.89,9.65 61.98,9.65 63.63,8 66.04,8 67.18,9.14 67.18,11.56 v1(68.96,13.34)
USB_I2C_SDA: length 132.7
  TOP w0.086: R363.1 68.7,13.97 v1(68.96,13.97) 69.09,13.84 U49.7 ; R362.2 35.69,14.35 v1(35.69,13.97) R364.2 ; v1(19.56,65.85) R85.1
  BOTTOM w0.086: v1(68.96,13.97) 66.93,11.94 66.93,9.27 65.91,8.26 63.75,8.26 62.1,9.91 49.02,9.91 47.62,11.3 40.64,11.3 37.97,13.97 v1(35.69,13.97) 34.42,12.7 34.42,11.43 33.78,10.8 25.78,10.8 18.67,17.91 10.16,17.91 6.6,21.46 4.83,21.46 3.75,22.54 3.75,36.77 6.73,39.75 6.73,53.02 v1(19.56,65.85)
USB_PD_VBUS:
  vias: v1(43.81,7.62)
USB_PD_VBUS_F: length 37
  TOP w0.203: v1(73.41,13.78) 73.34,13.84 U49.15
  TOP w0.254: U45.B2 U45.C2 U45.D2 U45.E2 U45.E1 ; R319.1 v1(68.83,18.42) 68.83,16.13 v1(69.6,15.37) ; R313.1 v1(69.85,22.1)
  TOP w0.381: D25.A v1(34.8,21.08)
  BOTTOM w0.254: v1(69.6,15.37) 69.6,14.73 69.85,14.48 72.71,14.48 v1(73.41,13.78) ; v1(64.77,18.54) 68.71,18.54 v1(68.83,18.42)
  BOTTOM w0.381: v1(34.8,21.08) 34.8,18.67 v1(40.77,12.7) ; v1(64.77,19.3) 68.45,19.3 69.85,20.7 v1(69.85,22.1)
  vias: v1(42.54,12.7) v1(43.43,12.7) v1(44.32,12.7) v1(45.21,12.7) v1(63.88,19.3) v1(63.88,18.54)
USBC_CC1: length 5.3
  TOP w0.086: J12.A5 29.09,8.75 TP173.1 28.32,9.53 28.32,10.16 27.09,11.4 U51.A1
USBC_CC2: length 17.8
  TOP w0.086: v1(31.75,9.27) TP174.1 34.04,9.27 35.31,8 35.31,5.72 34.04,4.45 31.47,4.45 J12.B5 ; U51.B1 27.49,11.38 28.77,10.1 v1(28.77,9.87)
  BOTTOM w0.086: v1(28.77,9.87) 28.98,9.65 29.85,9.65 30.35,10.16 30.86,10.16 v1(31.75,9.27)
USBC_DN: length 6.3
  TOP w0.087: J12.A7 30.09,7.74 v1(30.16,7.81) 29.95,8.02 29.95,8.78 U55.A1
  BOTTOM w0.087: J12.B7 29.44,6.58 29.59,6.73 29.72,6.73 29.85,6.6 30.08,6.6 30.65,7.17 30.65,8.13 30.48,8.29 30.08,8.29 29.95,8.17 29.95,8.02 v1(30.16,7.81)
USBC_DP: length 6.3
  TOP w0.087: J12.A6 29.59,7.75 v1(29.53,7.81) 29.74,8.02 29.74,8.78 U55.A2
  BOTTOM w0.087: v1(29.53,7.81) 29.74,8.02 29.74,8.26 29.99,8.51 30.57,8.51 30.86,8.22 30.86,7.08 30.24,6.46 J12.B6
USBC_EN_SNK1: length 1.7
  TOP w0.086: R370.1 31.1,12.42 U48.2
USBC_EN_SRC1: length 2.8
  TOP w0.086: U48.16 30.06,14.84 29.97,14.75 v1(29.97,12.95) R369.1
USBC_I2C_SCL: length 1.9
  TOP w0.086: R359.1 34.04,16.26 v1(33.66,16.26) 33.04,15.64 U48.8
USBC_I2C_SDA: length 1.7
  TOP w0.086: U48.7 v1(33.66,15.24) 33.91,14.99 R362.1
USBC_VBUS: length 12.5
  TOP w0.254: J12.A9 31.09,6.02 J12.B4 ; 27.81,8.38 28.59,7.6 J12.A4 28.59,6.02 J12.B9
  BOTTOM w0.381: J12.B4 31.62,6.55 31.62,8.51 30.99,9.14 29.59,9.14 28.64,8.2 J12.B9
USBC_VBUS_F: length 9
  TOP w0.203: U48.15 v1(29.34,15.24)
  TOP w0.254: U47.C4 U47.C5 U47.D5 U47.E5 U47.F5 U47.G5 ; U47.C4 U47.D4 U47.E4 U47.F4 U47.G4 ; U47.C4 U47.C3 U47.C2
  TOP w0.381: v1(24.66,10.52) F2.2 ; R288.1 v1(26.67,24) ; R294.1 v1(25.89,22.85) ; D24.A v1(25.15,19.3)
  vias: v1(16.26,18.42) v1(17.02,18.42) v1(17.91,18.42) v1(18.8,18.42)
VBBS: length 2.4
  TOP w0.254: C25.1 v1(16.76,73.53) 16.78,73.52 U12.14
VEN_SPI_CLK: length 2.2
  TOP w0.086: R351.1 128.79,16.12 J8.42
VEN_SPI_CS: length 1.4
  TOP w0.086: R324.1 v1(120.27,17.78) R344.2
VEN_SPI_MISO: length 2.4
  TOP w0.086: J8.40 v1(129.29,15.64) R352.1
VEN_SPI_MOSI: length 2.6
  TOP w0.086: R353.1 v1(130.3,15.62) 129.79,15.12 J8.38
VEXP_3V3: length 24.3
  TOP w0.381: J4.17 v1(114.3,78.74)
  BOTTOM w0.381: v1(92.96,77.34) 108.2,77.34 109.6,78.74 v1(114.3,78.74)
VEXP_5V:
  vias: v1(92.2,79.88)
VEXT_3V3: length 19.7
  TOP w0.254: R354.1 v1(134.11,17.53) ; R322.2 v1(133.99,19.43) ; R314.2 v1(119.13,15.88) ; R318.2 v1(140.59,21.08) ; R350.1 v1(127.76,15.24)
  TOP w0.381: R268.1 v1(135,26.8) ; C122.1 v1(136.02,26.54) ; D1.2 77.01,77.04 78.3,75.76 85.61,75.76 C16.1 ; C123.2 v1(138.05,26.54)
  vias: v1(86.87,76.07) v1(87.19,75.59) v1(118.36,13.59) v1(118.36,12.57) v1(120.14,14.35) v1(120.14,13.46) v1(121.03,12.7) v1(132.21,29.46) v1(134.11,29.46) v1(135.89,29.34) v1(137.16,29.34) v1(138.56,12.7) v1(139.45,14.35) v1(139.45,13.46) v1(141.22,13.59) v1(141.22,12.57)
VLDO1_3V3: length 1.7
  TOP w0.254: C182.1 18.54,14.61 18.7,14.77 U47.A5
VLDO_3V3: length 173.1
  TOP w0.254: R320.1 v1(70.48,19.06) ; R79.1 13.46,66.42 v1(12.83,66.42) ; U52.A3 75.29,8.24 C195.1 ; U47.A1 v1(20.66,14.7) ; 26.92,12.5 U51.A3
  TOP w0.381: v1(75.18,17.53) 75.18,13.59 73.53,11.94 73.53,9.27 ; R19.1 v1(12.7,76.07) ; v1(20.66,14.7) 23.84,14.7 25.59,16.45 U46.1 27.52,15.58 C175.1 C176.1 v1(26.92,13.21) 26.92,12.5 ; C195.1 66.93,8.13 v1(65.79,9.27) R374.1 ; D3.A v1(6.73,72.39)
  BOTTOM w0.254: v1(70.48,19.06) 73.65,19.06 v1(75.18,17.53)
  BOTTOM w0.381: v1(20.66,14.7) 20.61,14.7 C313.1 20.07,15.49 18.29,17.27 9.65,17.27 6.86,20.07 4.83,20.07 2.79,22.1 2.79,37.21 5.84,40.26 5.84,53.53 12.83,60.52 v1(12.83,66.42) 13.46,67.06 13.46,75.31 v1(12.7,76.07) 9.02,72.39 v1(6.73,72.39) ; v1(26.92,13.21) 27.3,13.59 30.23,13.59 31.24,12.57 32.69,12.57 33.07,12.95 33.07,14.22 33.45,14.61 37.97,14.61 40.77,11.81 47.75,11.81 49.21,10.35 62.29,10.35 63.94,8.7 65.21,8.7 v1(65.79,9.27)
VLS_3V3: length 84.7
  TOP w0.254: v1(54.93,49.4) 55.17,49.16 U19.4 ; v1(59.31,43.37) 59.19,43.25 U24.4
  TOP w0.381: C65.1 C66.1 v1(54.93,49.4) ; v1(65.66,41.53) 65.66,34.8 59.05,28.19 32.89,28.19 31.37,26.67 27.43,26.67 26.92,27.18 TP124.1 D19.C D18.C ; R214.1 58.81,44.95 v1(57.78,45.97)
  BOTTOM w0.381: C249.1 58.29,42.55 57.78,43.05 v1(57.78,45.97) 57.78,47.63 56.78,48.64 R436.1 56.77,49.14 R437.1 55.19,49.14 v1(54.93,49.4) ; C249.1 R438.1 65.65,41.52 v1(65.66,41.53) ; C249.1 59.18,43.24 v1(59.31,43.37) C243.1
VMIC_1V8: length 263.2
  TOP w0.254: C196.1 C197.1 v1(6.22,6.22) 5.33,6.22 4.49,7.07 U56.4 U56.3 ; U66.5 82.31,83.84 82.55,84.07 C1.1 ; U5.4 81.07,77.93 81.66,77.34 C14.1 C8.1 v1(83.19,83.31) ; v1(80.14,4.83) 81.91,4.83 81.91,6.23 81.07,7.07 U57.4 ; 8.51,76.84 C11.1 C10.1 5.59,76.84 4.49,77.93 U4.4 U4.3
  TOP w0.381: TP6.1 v1(11.18,84.71) ; v1(83.19,83.31) C1.1
  BOTTOM w0.254: v1(8.51,76.07) 6.22,73.79 6.22,71.12 10.41,66.93 10.41,58.93 2.03,50.55 2.03,13.78 4.38,11.43 5.21,11.43 7.3,9.33 7.3,7.3 v1(6.22,6.22) 9.46,2.98 51.5,2.98 52.32,2.16 67.69,2.16 68.64,3.11 78.42,3.11 v1(80.14,4.83)
  BOTTOM w0.381: v1(11.18,84.71) 80.14,84.71 80.77,84.07 82.42,84.07 v1(83.19,83.31)
VSD2_3V3: length 22
  TOP w0.254: U26.A1 136.78,39.88
  TOP w0.381: v1(128.76,54.63) 128.48,54.63 128.1,54.25 D10.1 C61.1 130.89,53.98 J6.4
  BOTTOM w0.508: v1(137.92,42.16) 137.92,48.01 131.3,54.63 v1(128.76,54.63)
VSD_3V3: length 107.7
  TOP w0.203: U23.33 47.39,40.76 v1(47.24,40.61) 47.31,40.55 C88.1
  TOP w0.254: U26.A2 136.78,38.86
  TOP w0.508: 137.03,35.56 125.98,35.56 v1(122.94,32.51)
  BOTTOM w0.508: v1(47.24,40.61) 46.48,39.85 46.48,38.1 48.01,36.58 52.5,36.58 54.03,38.1 58.67,38.1 61.02,40.45 73.22,40.45 76.2,37.47 81.53,37.47 83.06,38.99 88.07,38.99 89.73,40.64 97.79,40.64 109.35,29.08 119.51,29.08 v1(122.94,32.51)
VSYS: length 27.9
  TOP w0.203: U23.37 48.99,40.76 v1(49.05,40.7)
  TOP w0.381: R481.2 v1(34.16,30.87)
  L3_PWR w0.381: v1(34.16,30.87) 34.55,30.87 35.05,31.37 35.05,38.35 34.4,39 34.4,39.74 34.8,40.13 37.34,40.13 37.78,40.58 45.28,40.58 46.1,41.4 48.35,41.4 v1(49.05,40.7)
  BOTTOM w0.381: v1(49.05,40.7) 48.89,40.55 C254.2
VSYS_5V: length 19
  TOP w0.203: U23.2 51.5,42.67 v1(51.69,42.48) ; 30.48,31.5 30.73,31.5 31.13,31.89 31.13,34.15 25.65,39.62 20.96,39.62 R231.1 ; U23.40 50.19,41.25 50.55,40.89 v1(50.8,40.89)
  TOP w0.381: R481.1 v1(34.04,31.62)
  vias: v1(29.21,33.91) v1(29.21,33.02) v1(29.46,31.62) v1(30.1,33.91) v1(30.1,33.02) v1(44.07,44.2) v1(44.58,44.58) v1(44.58,43.94) v1(45.08,44.26) v1(51.59,44.45) v1(52.2,44.45) v1(52.83,44.45)
VSYS_5V_COMP: length 3
  TOP w0.254: U39.30 44.33,21.35 C160.1 R317.1
VSYS_5V_FB: length 7.1
  TOP w0.254: v1(44.58,20.7) 44.72,20.85 U39.31
  TOP w0.381: R341.2 42.67,16.9 C168.2 v1(43.56,17.78)
  BOTTOM w0.381: v1(43.56,17.78) 43.56,19.69 v1(44.58,20.7) R474.1
VSYS_EN: length 2.1
  TOP w0.254: R283.2 43.94,24.26 v1(44.85,23.35) U39.26
VTREF: length 2.5
  TOP w0.254: 75.44,25.4 v1(75.44,23.62) R300.2
WDOG_B: length 145.7
  TOP w0.086: TP59.1 44.58,52.07 v1(42.93,53.72) ; TP59.1 44.2,51.05 R188.1 ; TP59.1 44.78,51.44 45.47,52.12 47.93,52.12 48.13,52.32 48.13,55.88 48.51,56.26 53.21,56.26 55.12,58.17 65.91,58.17 67.69,56.39 67.69,44.13 v1(68.58,43.24) ; v2(96.73,52.87) U1.H14 ; R163.2 v1(107.95,53.98) 105.28,53.98 v1(104.77,53.47) ; Q3.1 v1(8.89,51.42)
  BOTTOM w0.086: v1(107.95,53.98) 107.95,50.8 101.35,44.2 98.81,44.2 98.11,44.89 90.61,44.89 89.15,43.43 83.06,43.43 82.68,43.05 68.77,43.05 v1(68.58,43.24) ; v1(8.89,51.42) 9.77,50.55 16.51,50.55 18.67,52.71 23.88,52.71 24.89,51.69 30.99,51.69 33.27,53.98 42.67,53.98 v1(42.93,53.72) ; v2(96.73,52.87) 96.74,52.87 97.8,51.82 103.12,51.82 v1(104.77,53.47)
XIN_32K: length 4.3
  TOP w0.086: QZ2.2 49.26,50.02 48.37,49.14 C70.1 48.37,48.11 48.27,48.01 R193.1 48.19,47.92 U23.16
XOUT_32K: length 4.3
  TOP w0.086: U23.17 47.79,47.96 R193.2 47.64,48.11 C69.1 47.64,49.14 46.76,50.02 QZ2.1
XTALI_24M: length 12.1
  TOP w0.086: C42.1 96.89,66.62 Y1.1 96.81,66.59 95.76,65.53 95.76,64.01 R105.1 95.12,63.37 TP31.1 94.23,61.34 U1.A9
XTALI_32K: length 10.1
  TOP w0.086: U1.A5 92.23,60.55 91.31,61.47 TP30.1 90.17,63.37 90.17,64.25 C48.1 90.16,64.63 90.91,65.38 QZ1.2
XTALO_24M: length 12.4
  TOP w0.086: C41.1 95.77,66.05 94.7,64.99 Y1.3 94.37,64.7 R105.2 94.37,61.86 93.99,61.47 93.99,56.58 U1.B9
XTALO_32K: length 11
  TOP w0.086: U1.B5 91.99,56.58 91.99,56.73 91.99,56.73 91.99,56.94 91.99,56.94 91.99,60.41 89.15,63.25 R104.2 89.15,64.25 C47.1 89.17,64.63 88.41,65.38 QZ1.1
N117383326: length 3.1
  TOP w0.086: R281.1 5.21,23.5 R296.2 5.01,23.31 v1(5.01,22.73) U42.1
N117385728: length 2.6
  BOTTOM w0.203: U64.11 39.45,32.82 39.63,32.64 C274.1 R460.2
N117385807: length 2.7
  BOTTOM w0.203: U64.12 38.95,32.17 39.5,31.62 C274.2 R461.2
N117385857: length 3.9
  BOTTOM w0.203: R466.2 C283.1 38.01,30.61 37.81,30.81 U64.13
N117385909: length 5.1
  BOTTOM w0.203: U64.14 37.16,30.66 38.23,29.59 C283.2 R469.2
N117385984: length 3.9
  BOTTOM w0.203: R448.2 C265.1 38.01,35.69 37.81,35.48 U64.8
N117385990: length 1.6
  BOTTOM w0.254: U64.6 36.5,36.65 R441.1
N117386025: length 2.8
  BOTTOM w0.254: R464.1 R463.1 33.3,31.62 33.85,32.17 U64.1
N117386063: length 5.1
  BOTTOM w0.203: U64.7 37.16,35.63 38.23,36.7 C265.2 R440.2
N117386111: length 1.8
  BOTTOM w0.254: R470.1 35.85,30.15 U64.16
N117386128: length 2.6
  BOTTOM w0.203: U64.10 39.45,33.47 39.63,33.66 C270.1 R459.2
N117386168: length 2.7
  BOTTOM w0.203: U64.9 38.95,34.12 39.5,34.67 C270.2 R450.2
N117386249: length 2.6
  TOP w0.203: R132.2 C53.1 v1(48.96,58.8) 48.78,58.62 U16.11
N117386325: length 2.7
  TOP w0.203: U16.12 48.35,59.27 v1(48.89,59.82) C53.2 R127.2
N117386356: length 1.6
  TOP w0.203: U16.13 47.2,60.54 v1(47.62,60.96) C51.1
N117386392: length 1.5
  TOP w0.203: U16.14 v1(46.55,61.02) 46.61,61.08 C51.2
N117386460: length 2.7
  TOP w0.203: R167.2 C59.1 v1(47.62,55.63) 47.2,56.05 U16.8
N117386466: length 1.6
  TOP w0.254: R162.1 v1(45.59,55.56) 45.9,55.87 U16.6
N117386498: length 2.9
  TOP w0.254: U16.1 43.6,59.27 v1(43.31,59.56) R128.1 R120.1
N117386536: length 2.5
  TOP w0.203: R166.2 C59.2 v1(46.61,55.56) 46.55,55.62 U16.7
N117386581: length 2.1
  TOP w0.254: R115.1 44.07,61.72 v1(44.83,60.96) 45.25,60.54 U16.16
N117386598: length 2.6
  TOP w0.203: U16.10 48.78,57.97 v1(48.96,57.79) C56.1 R134.2
N117386638: length 2.7
  TOP w0.203: R148.2 C56.2 v1(48.89,56.77) 48.35,57.32 U16.9
N117386716: length 2.6
  TOP w0.203: R152.2 C57.1 v1(31.31,55.5) 31.12,55.32 U17.11
N117386852: length 2.7
  TOP w0.203: R149.2 C57.2 v1(31.24,56.52) 30.69,55.97 U17.12
N117386899: length 2.7
  TOP w0.203: U17.13 29.55,57.24 v1(29.97,57.66) C55.1 R126.2
N117386951: length 2.5
  TOP w0.203: U17.14 v1(28.9,57.72) 28.96,57.78 R125.2
N117387023: length 2.7
  TOP w0.203: R184.2 C62.1 v1(29.97,52.26) 29.55,52.68 U17.8
N117387029: length 1.6
  TOP w0.254: U17.6 28.25,52.52 v1(27.94,52.21) R176.1
N117387061: length 2.9
  TOP w0.254: R145.1 R150.1 v1(25.53,56.26) 25.82,55.97 U17.1
N117387099: length 2.5
  TOP w0.203: U17.7 28.9,52.32 v1(28.96,52.26) R183.2
N117387144: length 2.8
  TOP w0.254: R124.1 v1(26.92,58.42) 27.6,57.74 U17.16
N117387161: length 2.6
  TOP w0.203: U17.10 31.12,54.67 v1(31.31,54.48) C60.1 R161.2
N117387201: length 2.7
  TOP w0.203: U17.9 30.69,54.02 v1(31.24,53.47) C60.2 R165.2
N117387282: length 2.6
  TOP w0.203: U21.11 22.61,45.66 v1(22.8,45.85) C72.1 R200.2
N117387358: length 2.7
  TOP w0.203: U21.12 22.18,46.31 v1(22.73,46.86) C72.2 R197.2
N117387408: length 2.7
  TOP w0.203: R182.2 C68.1 v1(21.46,48.07) 21.04,47.65 U21.13
N117387460: length 2.5
  TOP w0.203: R181.2 C68.2 20.45,48.13 v1(20.39,48.07) U21.14
N117387535: length 2.7
  TOP w0.203: R232.2 C85.1 v1(21.46,42.67) 21.04,43.09 U21.8
N117387541: length 1.6
  TOP w0.254: R230.1 v1(19.43,42.61) 19.74,42.92 U21.6
N117387573: length 2.7
  TOP w0.254: U21.1 v1(17.02,46.31) 16.42,46.31 R199.1 R195.1
N117387611: length 2.5
  TOP w0.203: R231.2 C85.2 v1(20.45,42.61) 20.39,42.66 U21.7
N117387659: length 3
  TOP w0.254: U21.16 19.09,47.97 v1(17.91,49.15) R180.1
N117387676: length 2.6
  TOP w0.203: R213.2 C79.1 v1(22.8,44.83) 22.61,45.01 U21.10
N117387716: length 2.7
  TOP w0.203: R220.2 C79.2 v1(22.73,43.82) 22.18,44.36 U21.9
N117391298: length 1.6
  TOP w0.254: U24.7 v1(59.19,40.01)
  BOTTOM w0.254: R438.2 59.18,40.02 v1(59.19,40.01)
N117391560: length 1.6
  TOP w0.254: v1(58.29,49.16) U19.7
  BOTTOM w0.254: R436.2 58.28,49.15 v1(58.29,49.16)
N117392496: length 3.1
  TOP w0.254: U33.5 22.55,32.99 C96.1 v1(22.51,33.72) 22.51,34.32 D19.A
N117392540: length 1.5
  TOP w0.254: U33.4 24.44,32.95 C97.1
N117392714: length 1.5
  TOP w0.086: R156.2 v1(16.89,54.11) 16.5,53.72 16.5,53.72 U18.1
N117392721: length 1.1
  TOP w0.086: U18.2 16,54.61 R155.2
N117395484: length 3
  TOP w0.086: R189.2 R190.2 46.35,48.01 47.39,46.97 U23.18
N117395690: length 3.5
  TOP w0.086: R188.2 44.2,47.63 44.58,47.24 46.35,47.24 46.59,47.01 U23.20
N117395722: length 2.3
  TOP w0.086: U23.15 48.59,47.35 49.24,48.01 R191.2
N117395724: length 7.7
  TOP w0.203: v1(52.2,42.04) 52.2,42.67 51.8,43.07 U23.3
  TOP w0.254: R242.1 R235.2 v1(54.1,39.38)
  BOTTOM w0.254: v1(52.2,42.04) 52.2,41.28 52.58,40.89 53.72,40.89 54.1,40.51 v1(54.1,39.38)
N117395763: length 2.6
  TOP w0.086: U23.31 46.59,41.38 46.48,41.28 45.97,41.28 45.21,40.51 R237.2
N117395797: length 7.7
  TOP w0.086: R169.2 50.93,52.08 50.93,47.63 50.61,47.31 50.1,47.31 49.79,46.99 U23.12
N117395822: length 8.1
  TOP w0.086: U23.13 49.39,46.97 49.97,47.56 50.48,47.56 50.67,47.75 50.67,51.31 R168.2
N117396221: length 3.3
  TOP w0.086: R236.2 45.47,41.14 45.47,42.16 45.57,42.27 U23.30
N117396699: length 1.1
  TOP w0.203: D28.A R382.2
N117397706: length 2
  TOP w0.254: U40.2 113.26,19.96 C162.1
N117397841: length 2
  TOP w0.254: U40.14 v1(104.27,20.61) 103.85,20.61 C157.2
N117397843: length 1.9
  TOP w0.254: U40.5 113.36,21.92 C149.1
N117397886: length 2
  TOP w0.254: U40.3 v1(112.65,20.61) 113.07,20.61 C149.2
N117397940: length 4.3
  TOP w0.086: R306.2 R307.1 102.94,21.53 103.82,21.53 104.21,21.92 U40.12
N117398055: length 1.4
  TOP w0.254: R334.1 102.49,17.64 C165.2
N117398057: length 1.4
  TOP w0.254: R337.1 114.43,17.64 C166.2
N117399431: length 3.8
  TOP w0.254: R43.1 C38.1 v1(31.62,68.07) 31.62,67.31 S1.2
N117399829: length 3.8
  TOP w0.254: S1.1 36.96,67.31 v1(36.96,68.07) C39.1 R44.2
N117400024: length 2.6
  TOP w0.381: D3.C v1(10.54,71.5) 10.92,71.88 R46.1
N117400223: length 3.1
  TOP w0.254: U12.1 15.78,68.23 15.37,67.82 v1(14.1,67.82) R79.2
N117400330: length 1.5
  TOP w0.254: U12.3 16.78,67.44 R82.2
N117400348: length 1.5
  TOP w0.254: U12.4 17.28,67.43 R83.2
N117400350: length 3.4
  TOP w0.086: U12.12 17.78,72.51 18.41,73.15 18.41,74.17 TP7.1
N117400364: length 2.2
  TOP w0.086: U12.8 19.28,68.23 19.43,68.07 19.94,68.07 20.7,67.31 TP24.1
N117400372: length 1.8
  TOP w0.086: TP11.1 19.28,72.24 U12.9
N117400380: length 3.5
  TOP w0.086: TP8.1 19.69,74.17 19.69,73.27 18.78,72.36 U12.10
N117400386: length 1.7
  TOP w0.086: TP10.1 18.28,72.51 U12.11
N117403125: length 3.9
  TOP w0.086: Q8.3 71.18,19.81 R320.2 R319.2 68.71,19.93 v1(68.2,19.93) U45.A3
N117403218: length 1.8
  TOP w0.254: R383.1 74.72,4.2 74.68,4.15 SW5.2
N117403229: length 1.8
  TOP w0.254: R381.2 74.72,6.6 74.67,6.65 SW5.3
N117403272: length 2
  TOP w0.254: SW5.5 68.23,4.15 R385.1
N117403287: length 2
  TOP w0.254: SW5.6 68.25,6.65 R380.2
N117403318: length 1.1
  TOP w0.086: TP172.1 74.22,10.49 U52.C3
N117403325: length 4.6
  TOP w0.254: R321.1 75.3,18.92 C163.1 73.33,18.92 Q8.1 v1(72.36,18.44) 71.88,17.96 R339.2
N117403441: length 2.2
  TOP w0.086: Q10.3 70.1,10.16 R375.2 R376.2
N117403643: length 1.9
  TOP w0.086: R338.1 70.45,16.17 U49.5
N117404021: length 12
  TOP w0.254: U39.27 44.59,22.85 v1(43.81,23.62)
  TOP w0.381: v1(43.82,16.38) R360.1 C173.1
  BOTTOM w0.381: v1(43.81,23.62) 43.43,23.62 42.93,23.11 42.93,17.28 v1(43.82,16.38)
N117404068: length 1.8
  TOP w0.254: U58.5 54.24,4.66 v1(54.03,4.45)
  BOTTOM w0.254: 54.03,3.3 v1(54.03,4.45)
N117404089: length 2.1
  TOP w0.254: U58.6 v1(54.74,4.45)
  BOTTOM w0.086: v1(54.74,4.45) 54.33,4.85 53.49,4.85 R478.1
N117404099: length 3.3
  TOP w0.254: U39.19 v1(48.76,25.27)
  BOTTOM w0.254: v1(48.76,25.27) 48.13,24.65 C306.1
N117404161: length 3.6
  TOP w0.086: U58.2 v1(55.24,7.49)
  BOTTOM w0.086: v1(55.24,7.49) 54.83,7.09 53.49,7.09 R476.2 R477.2
N117404173: length 1
  BOTTOM w0.254: C306.2 v3(48.13,20.96)
  vias: v3(48.51,20.45) v3(48.89,20.96) v3(49.66,20.45) v3(49.78,21.34)
N117404204: length 10.3
  TOP w0.381: R360.2 44.57,16.38 v1(44.58,16.38)
  BOTTOM w0.381: v1(44.58,16.38) 46.35,14.61 v1(53.47,14.61)
N117404484: length 1.2
  TOP w0.254: C159.1 41.69,19.81 R317.2
N117417066: length 2
  TOP w0.254: C78.1 61.72,43.56 v1(61.47,43.31) 60.96,43.31 60.69,43.04 U24.1
N117417617: length 1.8
  TOP w0.254: U19.1 55.54,50.89 v1(54.99,51.44) C63.1
N117424543: length 2
  TOP w0.086: U2.G11 79.49,47.31 v2(78.91,47.31)
  BOTTOM w0.086: v2(78.91,47.31) 78.56,47.31 78.56,47.31 R102.2
N117426825: length 8.1
  TOP w0.086: U1.A3 91.23,59.26 88.01,62.48 R114.1
N117433736: length 6
  TOP w0.086: TP103.1 105.16,40.77 109.51,40.77 U25.K5
N117434649: length 8.7
  TOP w0.086: U26.B2 v1(136.02,38.61) ; R216.2 v1(131.95,44.45)
  BOTTOM w0.086: v1(136.02,38.61) 136.02,40.38 v1(131.95,44.45)
N117439420: length 8.2
  TOP w0.086: U15.30 113.17,61.73 112.84,61.4 112.84,61.02 113.37,60.49 113.37,59.78 113.03,59.44 111.13,59.44 111,59.31 R130.2 v1(110.36,58.93) R129.2
  BOTTOM w0.086: v1(110.36,58.93) R130.2
N117439422: length 8.3
  TOP w0.086: R121.2 v1(110.36,60.2) R122.2 111,59.82 111.13,59.69 112.9,59.69 113.12,59.91 113.12,60.36 112.59,60.9 112.59,61.53 113.29,62.23 U15.29
  BOTTOM w0.086: v1(110.36,60.2) R122.2
N117439424: length 4.6
  TOP w0.086: U15.28 113.16,62.73 v1(113.03,62.61) 112.33,62.61 112.33,62.61 C49.1 111.89,61.73 R118.2
  BOTTOM w0.086: v1(113.03,62.61) 113.64,62.61 114.02,62.22 R430.2
N117439483: length 2.7
  TOP w0.086: R137.1 v1(113.92,58.93) 114.3,58.93 114.96,59.59 U15.1
N117439503: length 2.5
  TOP w0.086: U15.2 115.46,59.2 115.19,58.93 v1(114.94,58.93) R138.1
N117439523: length 2.1
  TOP w0.086: U15.3 v1(115.96,58.94) R139.1
N117439558: length 1.9
  TOP w0.086: U15.4 116.46,58.42 R140.1
N117439590: length 1.9
  TOP w0.086: R141.1 116.96,58.42 v1(116.96,58.93) U15.5
N117439655: length 2.1
  TOP w0.086: R142.1 117.46,58.94 U15.6
N117439684: length 1.9
  TOP w0.086: SW4.2 v1(137.48,69.09) R63.1
N117439704: length 4.7
  TOP w0.086: U15.32 113.88,60.73 113.79,60.65 v1(113.79,60.2) 113.79,59.68 R136.2 R135.2
N117439710: length 2.5
  TOP w0.086: U15.7 117.96,59.2 v1(118.24,58.93) 118.49,58.67 118.74,58.67 R143.1
N117439737: length 1.9
  TOP w0.086: R67.1 v1(137.48,67.82) SW4.4
N117439768: length 2.9
  TOP w0.086: U15.8 118.46,59.34 118.87,58.93 v1(119.51,58.93) R144.1
N117439790: length 1.9
  TOP w0.086: R90.1 v1(137.48,66.55) 136.27,66.55
N117439833: length 1.9
  TOP w0.086: SW4.8 v1(137.48,65.28) R97.1
